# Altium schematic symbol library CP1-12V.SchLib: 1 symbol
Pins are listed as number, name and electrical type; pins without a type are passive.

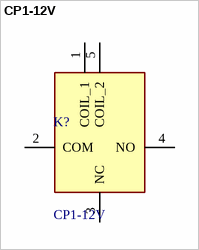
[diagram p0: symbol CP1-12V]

## CP1-12V
designator K?
PANASONIC ELECTRIC WORKS - CP1-12V - RELAY, AUTOMOTIVE, SPDT, 14VDC, 20A; Geometry.Height: 9.5mm
footprint CP112V
pins: 1 COIL_1, 2 COM, 3 NC, 4 NO, 5 COIL_2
